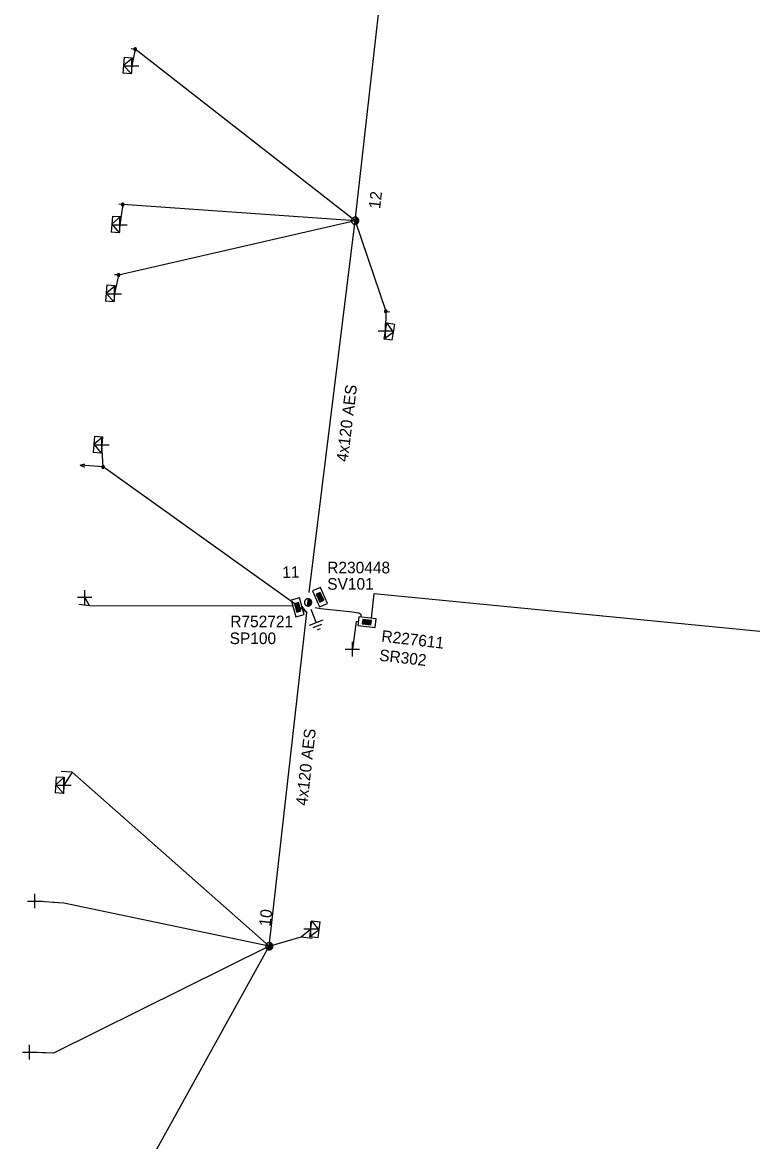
# Model space of a CAD drawing. Extents: x -544780 to -541582, y -1198995 to -1196551.
# Drawn here: x -543862.4 to -543799.3, y -1197255.8 to -1197159.1 of the extents above; entities that cross this region are included whole.
import ezdxf

# ---------------------------------------------------------------- set-up
doc = ezdxf.new("R2010")
doc.units = 0
for name, color, linetype in [('Vrstva 1', 7, 'Continuous'), ('Vrstva 13', 7, 'Continuous'), ('Vrstva 14', 7, 'Continuous'), ('Vrstva 15', 7, 'Continuous'), ('Vrstva 2', 7, 'Continuous'), ('Vrstva 28', 7, 'Continuous'), ('Vrstva 29', 7, 'Continuous'), ('Vrstva 30', 7, 'Continuous'), ('Vrstva 31', 7, 'Continuous'), ('Vrstva 34', 7, 'Continuous'), ('Vrstva 5', 7, 'Continuous'), ('Vrstva 50', 7, 'Continuous'), ('Vrstva 51', 7, 'Continuous'), ('Vrstva 52', 7, 'Continuous'), ('Vrstva 54', 7, 'Continuous'), ('Vrstva 59', 7, 'Continuous'), ('Vrstva 8', 7, 'Continuous'), ('Vrstva 9', 7, 'Continuous')]:
    doc.layers.add(name, color=color, linetype=linetype)

# ---------------------------------------------------------------- blocks, each defined once
blk = doc.blocks.new('NN440')
at = {"layer": 'Vrstva 2'}
for points in [[(0.63, 0), (0.63, 0.06), (0.62, 0.13), (0.6, 0.19), (0.58, 0.25), (0.55, 0.31), (0.51, 0.37), (0.47, 0.42), (0.42, 0.46), (0.37, 0.51), (0.32, 0.54), (0.26, 0.57), (0.2, 0.59), (0.13, 0.61), (0.07, 0.62), (0, 0.63), (-0.06, 0.62), (-0.13, 0.61), (-0.19, 0.59), (-0.26, 0.57), (-0.31, 0.54), (-0.37, 0.51), (-0.42, 0.46), (-0.47, 0.42), (-0.51, 0.37), (-0.54, 0.31), (-0.57, 0.25), (-0.6, 0.19), (-0.62, 0.13), (-0.63, 0.06), (-0.63, 0), (-0.63, -0.07), (-0.62, -0.14), (-0.6, -0.2), (-0.57, -0.26), (-0.54, -0.32), (-0.51, -0.37), (-0.47, -0.43), (-0.42, -0.47), (-0.37, -0.51), (-0.31, -0.55), (-0.26, -0.58), (-0.19, -0.6), (-0.13, -0.62), (-0.06, -0.63), (0, -0.63), (0.07, -0.63), (0.13, -0.62), (0.2, -0.6), (0.26, -0.58), (0.32, -0.55), (0.37, -0.51), (0.42, -0.47), (0.47, -0.43), (0.51, -0.37), (0.55, -0.32), (0.58, -0.26), (0.6, -0.2), (0.62, -0.14), (0.63, -0.07), (0.63, 0)], [(-0.63, 0), (0.63, 0)], [(-0.6, -0.18), (0.57, -0.18)], [(-0.51, -0.32), (0.5, -0.32)], [(-0.37, -0.47), (0.35, -0.47)]]:
    blk.add_lwpolyline(points, dxfattribs=at)
blk = doc.blocks.new('NN560')
at = {"layer": 'Vrstva 2'}
for points in [[(1.999, -0.001), (1.59, 0.141)], [(0, -0.001), (1.999, -0.001)], [(1.999, -0.001), (1.59, -0.134)]]:
    blk.add_lwpolyline(points, dxfattribs=at)
blk = doc.blocks.new('NN800')
at = {"layer": 'Vrstva 1'}
for points in [[(-0.442, 0.442), (0.442, -0.442)], [(-0.442, -0.442), (0.442, 0.442)]]:
    blk.add_lwpolyline(points, dxfattribs=at)
blk = doc.blocks.new('NN620')
at = {"layer": 'Vrstva 8'}
for points in [[(0.752, 0.004), (-0.748, 0.004)], [(-0.748, 0.004), (-0.748, -0.746)], [(0.752, -0.746), (0.752, 0.004)], [(-0.748, -0.746), (0.752, -0.746)], [(0.368, -0.18), (-0.376, -0.18)], [(-0.376, -0.18), (-0.376, -0.558)], [(-0.376, -0.558), (0.368, -0.558)], [(0.321, -0.227), (-0.329, -0.227)], [(-0.329, -0.227), (-0.329, -0.51)], [(-0.329, -0.51), (0.321, -0.51)], [(0.274, -0.274), (-0.281, -0.274)], [(-0.281, -0.274), (-0.281, -0.463)], [(-0.281, -0.463), (0.274, -0.463)], [(0.227, -0.321), (-0.234, -0.321)], [(-0.234, -0.321), (-0.234, -0.416)], [(-0.234, -0.416), (0.227, -0.416)], [(-0.193, -0.369), (0.185, -0.369)], [(0.227, -0.416), (0.227, -0.321)], [(0.274, -0.463), (0.274, -0.274)], [(0.321, -0.51), (0.321, -0.227)], [(0.368, -0.558), (0.368, -0.18)]]:
    blk.add_lwpolyline(points, dxfattribs=at)
blk = doc.blocks.new('NN630')
at = {"layer": 'Vrstva 9'}
for points in [[(-0.003, -0.7), (-0.703, 0)], [(-0.703, -0.7), (-0.703, 0), (0.697, 0), (0.697, -0.7)], [(-0.703, -0.7), (0.697, -0.7)], [(-0.003, -0.7), (0.697, 0)]]:
    blk.add_lwpolyline(points, dxfattribs=at)
blk = doc.blocks.new('NN810')
at = {"layer": 'Vrstva 14'}
for points in [[(0.004, -0.64), (0.004, -1.89)], [(0.629, -1.89), (-0.621, -1.89)], [(0.388, -2.2), (-0.399, -2.2)], [(0.004, -2.515), (-0.124, -2.515)], [(0.137, -2.515), (0.004, -2.515)]]:
    blk.add_lwpolyline(points, dxfattribs=at)
blk = doc.blocks.new('NN500')
at = {"layer": 'Vrstva 2'}
for points in [[(0, -0.24), (0.02, -0.23), (0.05, -0.23), (0.07, -0.22), (0.09, -0.22), (0.12, -0.2), (0.14, -0.19), (0.16, -0.18), (0.17, -0.16), (0.19, -0.14), (0.2, -0.12), (0.21, -0.1), (0.22, -0.07), (0.23, -0.05), (0.23, -0.02), (0.23, 0), (0.23, 0.02), (0.23, 0.05), (0.22, 0.07), (0.21, 0.1), (0.2, 0.12), (0.19, 0.14), (0.17, 0.16), (0.16, 0.17), (0.14, 0.19), (0.12, 0.2), (0.09, 0.21), (0.07, 0.22), (0.05, 0.23), (0.02, 0.23), (0, 0.23), (-0.03, 0.23), (-0.05, 0.23), (-0.07, 0.22), (-0.1, 0.21), (-0.12, 0.2), (-0.14, 0.19), (-0.16, 0.17), (-0.18, 0.16), (-0.19, 0.14), (-0.2, 0.12), (-0.22, 0.1), (-0.22, 0.07), (-0.23, 0.05), (-0.23, 0.02), (-0.24, 0), (-0.23, -0.02), (-0.23, -0.05), (-0.22, -0.07), (-0.22, -0.1), (-0.2, -0.12), (-0.19, -0.14), (-0.18, -0.16), (-0.16, -0.18), (-0.14, -0.19), (-0.12, -0.2), (-0.1, -0.22), (-0.07, -0.22), (-0.05, -0.23), (-0.03, -0.23), (0, -0.24)], [(0, -0.24), (0.02, -0.23), (0.05, -0.23), (0.07, -0.22), (0.09, -0.22), (0.12, -0.2), (0.14, -0.19), (0.16, -0.18), (0.17, -0.16), (0.19, -0.14), (0.2, -0.12), (0.21, -0.1), (0.22, -0.07), (0.23, -0.05), (0.23, -0.02), (0.23, 0), (0.23, 0.02), (0.23, 0.05), (0.22, 0.07), (0.21, 0.1), (0.2, 0.12), (0.19, 0.14), (0.17, 0.16), (0.16, 0.17), (0.14, 0.19), (0.12, 0.2), (0.09, 0.21), (0.07, 0.22), (0.05, 0.23), (0.02, 0.23), (0, 0.23), (-0.03, 0.23), (-0.05, 0.23), (-0.07, 0.22), (-0.1, 0.21), (-0.12, 0.2), (-0.14, 0.19), (-0.16, 0.17), (-0.18, 0.16), (-0.19, 0.14), (-0.2, 0.12), (-0.22, 0.1), (-0.22, 0.07), (-0.23, 0.05), (-0.23, 0.02), (-0.24, 0), (-0.23, -0.02), (-0.23, -0.05), (-0.22, -0.07), (-0.22, -0.1), (-0.2, -0.12), (-0.19, -0.14), (-0.18, -0.16), (-0.16, -0.18), (-0.14, -0.19), (-0.12, -0.2), (-0.1, -0.22), (-0.07, -0.22), (-0.05, -0.23), (-0.03, -0.23), (0, -0.24)], [(0, -0.21), (0.02, -0.2), (0.04, -0.2), (0.06, -0.2), (0.08, -0.19), (0.1, -0.18), (0.12, -0.17), (0.14, -0.15), (0.15, -0.14), (0.16, -0.12), (0.18, -0.1), (0.19, -0.08), (0.19, -0.06), (0.2, -0.04), (0.2, -0.02), (0.2, 0), (0.2, 0.02), (0.2, 0.04), (0.19, 0.06), (0.19, 0.08), (0.18, 0.1), (0.16, 0.12), (0.15, 0.14), (0.14, 0.15), (0.12, 0.17), (0.1, 0.18), (0.08, 0.19), (0.06, 0.19), (0.04, 0.2), (0.02, 0.2), (0, 0.2), (-0.02, 0.2), (-0.04, 0.2), (-0.06, 0.19), (-0.08, 0.19), (-0.1, 0.18), (-0.12, 0.17), (-0.14, 0.15), (-0.15, 0.14), (-0.17, 0.12), (-0.18, 0.1), (-0.19, 0.08), (-0.2, 0.06), (-0.2, 0.04), (-0.21, 0.02), (-0.21, 0), (-0.21, -0.02), (-0.2, -0.04), (-0.2, -0.06), (-0.19, -0.08), (-0.18, -0.1), (-0.17, -0.12), (-0.15, -0.14), (-0.14, -0.15), (-0.12, -0.17), (-0.1, -0.18), (-0.08, -0.19), (-0.06, -0.2), (-0.04, -0.2), (-0.02, -0.2), (0, -0.21)], [(0, -0.18), (0.02, -0.18), (0.04, -0.17), (0.05, -0.17), (0.07, -0.16), (0.09, -0.15), (0.1, -0.14), (0.12, -0.13), (0.13, -0.12), (0.14, -0.1), (0.15, -0.09), (0.16, -0.07), (0.17, -0.05), (0.17, -0.04), (0.17, -0.02), (0.17, 0), (0.17, 0.02), (0.17, 0.04), (0.17, 0.05), (0.16, 0.07), (0.15, 0.09), (0.14, 0.1), (0.13, 0.12), (0.12, 0.13), (0.1, 0.14), (0.09, 0.15), (0.07, 0.16), (0.05, 0.17), (0.04, 0.17), (0.02, 0.17), (0, 0.18), (-0.02, 0.17), (-0.04, 0.17), (-0.06, 0.17), (-0.07, 0.16), (-0.09, 0.15), (-0.1, 0.14), (-0.12, 0.13), (-0.13, 0.12), (-0.14, 0.1), (-0.15, 0.09), (-0.16, 0.07), (-0.17, 0.05), (-0.17, 0.04), (-0.18, 0.02), (-0.18, 0), (-0.18, -0.02), (-0.17, -0.04), (-0.17, -0.05), (-0.16, -0.07), (-0.15, -0.09), (-0.14, -0.1), (-0.13, -0.12), (-0.12, -0.13), (-0.1, -0.14), (-0.09, -0.15), (-0.07, -0.16), (-0.06, -0.17), (-0.04, -0.17), (-0.02, -0.18), (0, -0.18)], [(0, -0.15), (0.01, -0.15), (0.03, -0.14), (0.04, -0.14), (0.06, -0.13), (0.07, -0.13), (0.08, -0.12), (0.1, -0.11), (0.11, -0.1), (0.12, -0.09), (0.13, -0.07), (0.13, -0.06), (0.14, -0.05), (0.14, -0.03), (0.14, -0.02), (0.14, 0), (0.14, 0.01), (0.14, 0.03), (0.14, 0.04), (0.13, 0.06), (0.13, 0.07), (0.12, 0.09), (0.11, 0.1), (0.1, 0.11), (0.08, 0.12), (0.07, 0.13), (0.06, 0.13), (0.04, 0.14), (0.03, 0.14), (0.01, 0.14), (0, 0.15), (-0.02, 0.14), (-0.03, 0.14), (-0.05, 0.14), (-0.06, 0.13), (-0.07, 0.13), (-0.09, 0.12), (-0.1, 0.11), (-0.11, 0.1), (-0.12, 0.09), (-0.13, 0.07), (-0.13, 0.06), (-0.14, 0.04), (-0.14, 0.03), (-0.15, 0.01), (-0.15, 0), (-0.15, -0.02), (-0.14, -0.03), (-0.14, -0.05), (-0.13, -0.06), (-0.13, -0.07), (-0.12, -0.09), (-0.11, -0.1), (-0.1, -0.11), (-0.09, -0.12), (-0.07, -0.13), (-0.06, -0.13), (-0.05, -0.14), (-0.03, -0.14), (-0.02, -0.15), (0, -0.15)], [(0, -0.12), (0.01, -0.12), (0.02, -0.11), (0.03, -0.11), (0.05, -0.11), (0.06, -0.1), (0.07, -0.09), (0.08, -0.09), (0.09, -0.08), (0.09, -0.07), (0.1, -0.06), (0.11, -0.05), (0.11, -0.04), (0.11, -0.02), (0.11, -0.01), (0.12, 0), (0.11, 0.01), (0.11, 0.02), (0.11, 0.04), (0.11, 0.05), (0.1, 0.06), (0.09, 0.07), (0.09, 0.08), (0.08, 0.09), (0.07, 0.09), (0.06, 0.1), (0.05, 0.11), (0.03, 0.11), (0.02, 0.11), (0.01, 0.12), (0, 0.12), (-0.01, 0.12), (-0.03, 0.11), (-0.04, 0.11), (-0.05, 0.11), (-0.06, 0.1), (-0.07, 0.09), (-0.08, 0.09), (-0.09, 0.08), (-0.1, 0.07), (-0.1, 0.06), (-0.11, 0.05), (-0.11, 0.04), (-0.12, 0.02), (-0.12, 0.01), (-0.12, 0), (-0.12, -0.01), (-0.12, -0.02), (-0.11, -0.04), (-0.11, -0.05), (-0.1, -0.06), (-0.1, -0.07), (-0.09, -0.08), (-0.08, -0.09), (-0.07, -0.09), (-0.06, -0.1), (-0.05, -0.11), (-0.04, -0.11), (-0.03, -0.11), (-0.01, -0.12), (0, -0.12)], [(0, -0.09), (0.01, -0.09), (0.02, -0.09), (0.03, -0.08), (0.03, -0.08), (0.04, -0.08), (0.05, -0.07), (0.06, -0.07), (0.06, -0.06), (0.07, -0.05), (0.07, -0.04), (0.08, -0.04), (0.08, -0.03), (0.08, -0.02), (0.09, -0.01), (0.09, 0), (0.09, 0.01), (0.08, 0.02), (0.08, 0.03), (0.08, 0.03), (0.07, 0.04), (0.07, 0.05), (0.06, 0.06), (0.06, 0.06), (0.05, 0.07), (0.04, 0.07), (0.03, 0.08), (0.03, 0.08), (0.02, 0.08), (0.01, 0.09), (0, 0.09), (-0.01, 0.09), (-0.02, 0.08), (-0.03, 0.08), (-0.04, 0.08), (-0.04, 0.07), (-0.05, 0.07), (-0.06, 0.06), (-0.07, 0.06), (-0.07, 0.05), (-0.08, 0.04), (-0.08, 0.03), (-0.08, 0.03), (-0.09, 0.02), (-0.09, 0.01), (-0.09, 0), (-0.09, -0.01), (-0.09, -0.02), (-0.08, -0.03), (-0.08, -0.04), (-0.08, -0.04), (-0.07, -0.05), (-0.07, -0.06), (-0.06, -0.07), (-0.05, -0.07), (-0.04, -0.08), (-0.04, -0.08), (-0.03, -0.08), (-0.02, -0.09), (-0.01, -0.09), (0, -0.09)], [(0, -0.06), (0, -0.06), (0.01, -0.06), (0.02, -0.05), (0.02, -0.05), (0.03, -0.05), (0.03, -0.05), (0.04, -0.04), (0.04, -0.04), (0.05, -0.03), (0.05, -0.03), (0.05, -0.02), (0.05, -0.02), (0.05, -0.01), (0.06, -0.01), (0.06, 0), (0.06, 0.01), (0.05, 0.01), (0.05, 0.02), (0.05, 0.02), (0.05, 0.03), (0.05, 0.03), (0.04, 0.04), (0.04, 0.04), (0.03, 0.05), (0.03, 0.05), (0.02, 0.05), (0.02, 0.05), (0.01, 0.06), (0, 0.06), (0, 0.06), (-0.01, 0.06), (-0.01, 0.06), (-0.02, 0.05), (-0.02, 0.05), (-0.03, 0.05), (-0.03, 0.05), (-0.04, 0.04), (-0.04, 0.04), (-0.05, 0.03), (-0.05, 0.03), (-0.05, 0.02), (-0.06, 0.02), (-0.06, 0.01), (-0.06, 0.01), (-0.06, 0), (-0.06, -0.01), (-0.06, -0.01), (-0.06, -0.02), (-0.05, -0.02), (-0.05, -0.03), (-0.05, -0.03), (-0.04, -0.04), (-0.04, -0.04), (-0.03, -0.05), (-0.03, -0.05), (-0.02, -0.05), (-0.02, -0.05), (-0.01, -0.06), (-0.01, -0.06), (0, -0.06)], [(0, -0.03), (0, -0.03), (0, -0.03), (0.01, -0.03), (0.01, -0.03), (0.01, -0.02), (0.02, -0.02), (0.02, -0.02), (0.02, -0.02), (0.02, -0.02), (0.02, -0.01), (0.02, -0.01), (0.03, -0.01), (0.03, -0.01), (0.03, 0), (0.03, 0), (0.03, 0), (0.03, 0.01), (0.03, 0.01), (0.02, 0.01), (0.02, 0.01), (0.02, 0.02), (0.02, 0.02), (0.02, 0.02), (0.02, 0.02), (0.01, 0.02), (0.01, 0.02), (0.01, 0.03), (0, 0.03), (0, 0.03), (0, 0.03), (0, 0.03), (-0.01, 0.03), (-0.01, 0.03), (-0.01, 0.02), (-0.02, 0.02), (-0.02, 0.02), (-0.02, 0.02), (-0.02, 0.02), (-0.02, 0.02), (-0.03, 0.01), (-0.03, 0.01), (-0.03, 0.01), (-0.03, 0.01), (-0.03, 0), (-0.03, 0), (-0.03, 0), (-0.03, -0.01), (-0.03, -0.01), (-0.03, -0.01), (-0.03, -0.01), (-0.02, -0.02), (-0.02, -0.02), (-0.02, -0.02), (-0.02, -0.02), (-0.02, -0.02), (-0.01, -0.03), (-0.01, -0.03), (-0.01, -0.03), (0, -0.03), (0, -0.03)], [(0.23, 0), (0.7, 0)]]:
    blk.add_lwpolyline(points, dxfattribs=at)
blk = doc.blocks.new('NN510')
at = {"layer": 'Vrstva 2'}
blk.add_lwpolyline([(0.001, 0.002), (0.001, 0.939)], dxfattribs=at)

msp = doc.modelspace()

# ---------------------------------------------------------------- linework, layer by layer
at = {"layer": 'Vrstva 5'}
msp.add_lwpolyline([(-543837.124, -1197209.675), (-543836.658, -1197209.748), (-543834.156, -1197210.005), (-543833.342, -1197210.137), (-543833.188, -1197210.236), (-543833.186, -1197210.5)], dxfattribs=at)
at = {"layer": 'Vrstva 50'}
for points in [[(-543837.625, -1197208.372), (-543833.669, -1197176.26), (-543830.03, -1197144.12), (-543825.63, -1197110.859), (-543822.01, -1197079.019), (-543818.84, -1197052.008), (-543814.82, -1197018.239), (-543812.847, -1196994.699)], [(-543837.836, -1197210.101), (-543838.273, -1197209.553)], [(-543840.42, -1197347.53), (-543854.759, -1197329.329), (-543856.46, -1197300.73), (-543856.72, -1197267.15), (-543841.08, -1197238.92), (-543837.836, -1197210.101)]]:
    msp.add_lwpolyline(points, dxfattribs=at)
at = {"layer": 'Vrstva 52'}
msp.add_lwpolyline([(-543832.24, -1197210.609), (-543832.012, -1197208.446), (-543784.287, -1197213.107), (-543783.69, -1197208.582)], dxfattribs=at)
at = {"layer": 'Vrstva 54'}
for points in [[(-543833.669, -1197176.26), (-543854.092, -1197180.948), (-543854.457, -1197182.564)], [(-543833.669, -1197176.26), (-543831.026, -1197184.079), (-543831.042, -1197185.778)]]:
    msp.add_lwpolyline(points, dxfattribs=at)
at = {"layer": 'Vrstva 59'}
msp.add_lwpolyline([(-543833.404, -1197210.896), (-543833.586, -1197210.877), (-543833.901, -1197213.269)], dxfattribs=at)
at = {"layer": 'Vrstva 8'}
for points in [[(-543833.669, -1197176.26), (-543852.661, -1197161.446), (-543852.96, -1197162.877)], [(-543833.669, -1197176.26), (-543853.734, -1197174.865), (-543853.982, -1197176.608)], [(-543837.836, -1197210.101), (-543855.43, -1197197.524), (-543855.532, -1197195.626)], [(-543838.977, -1197209.549), (-543856.592, -1197209.512), (-543857.014, -1197208.78)], [(-543841.08, -1197238.92), (-543858.111, -1197223.887), (-543858.823, -1197225.02)], [(-543841.08, -1197238.92), (-543858.824, -1197235.194), (-543861.327, -1197235.015)], [(-543841.08, -1197238.92), (-543838.317, -1197238.097), (-543837.481, -1197237.421)], [(-543841.08, -1197238.92), (-543859.718, -1197248.166), (-543861.774, -1197248.076)]]:
    msp.add_lwpolyline(points, dxfattribs=at)

# ---------------------------------------------------------------- block references
at = {"layer": 'Vrstva 13'}
for name, p, xscale, yscale, rotation in [('NN500', (-543852.661, -1197161.446), 0.4999999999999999, 0.49999999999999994, 175.3009999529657), ('NN500', (-543853.734, -1197174.865), 0.5000000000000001, 0.5, 175.79799998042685), ('NN440', (-543833.67, -1197176.259), 0.5, 0.5000000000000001, 83.01446670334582), ('NN500', (-543854.092, -1197180.948), 0.5, 0.49999999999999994, 175.26399991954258), ('NN500', (-543831.026, -1197184.079), 0.5, 0.49999999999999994, -8.745999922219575), ('NN500', (-543855.43, -1197197.524), 0.5000000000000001, 0.5, 175.31999998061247), ('NN440', (-543837.73, -1197209.219), 0.5, 0.49999999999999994, 82.96938608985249), ('NN440', (-543841.08, -1197238.919), 0.5, 0.5, 83.63215273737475)]:
    msp.add_blockref(name, p, dxfattribs=dict(at, xscale=xscale, yscale=yscale, rotation=rotation))
for name, p, rotation in [('NN560', (-543855.43, -1197197.524), 175.3201750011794), ('NN510', (-543856.592, -1197209.513), 82.81437501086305), ('NN510', (-543858.111, -1197223.887), 87.0927389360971), ('NN510', (-543858.824, -1197235.195), 86.46965277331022), ('NN510', (-543838.318, -1197238.096), -96.94551112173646), ('NN510', (-543859.717, -1197248.167), 87.05653335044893)]:
    msp.add_blockref(name, p, dxfattribs=dict(at, rotation=rotation))
at = {"layer": 'Vrstva 15', "rotation": 21.168366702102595}
msp.add_blockref('NN810', (-543837.729, -1197209.218), dxfattribs=at)
at = {"layer": 'Vrstva 28'}
for p, rotation in [((-543837.042, -1197208.92), 113.4430000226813), ((-543838.273, -1197209.553), -73.8399472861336), ((-543832.613, -1197210.566), -6.580630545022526)]:
    msp.add_blockref('NN620', p, dxfattribs=dict(at, rotation=rotation))
at = {"layer": 'Vrstva 31'}
for p, rotation in [((-543852.96, -1197162.877), -94.69930275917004), ((-543853.982, -1197176.608), -94.20242503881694), ((-543854.457, -1197182.565), -94.73558331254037), ((-543831.042, -1197185.779), 81.2538388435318), ((-543855.532, -1197195.626), -94.67982498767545), ((-543858.823, -1197225.02), -92.90726105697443), ((-543837.481, -1197237.421), 82.90159441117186)]:
    msp.add_blockref('NN630', p, dxfattribs=dict(at, rotation=rotation))
at = {"layer": 'Vrstva 34'}
for p, rotation in [((-543852.96, -1197162.876), 45), ((-543853.982, -1197176.607), 45), ((-543854.457, -1197182.564), 45), ((-543831.042, -1197185.778), 45), ((-543855.532, -1197195.625), 45), ((-543857.014, -1197208.78), 45), ((-543833.901, -1197213.269), 44.99999995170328), ((-543858.823, -1197225.019), 45), ((-543861.327, -1197235.015), 45), ((-543837.481, -1197237.421), 45), ((-543861.774, -1197248.076), 45)]:
    msp.add_blockref('NN800', p, dxfattribs=dict(at, rotation=rotation))

# ---------------------------------------------------------------- texts
at = {"layer": 'Vrstva 14'}
for s, rotation, p in [('12', 83.014, (-543831.516, -1197175.261)), ('11', 1.133, (-543839.953, -1197207.118)), ('10', 83.632, (-543840.98, -1197237.259))]:
    msp.add_text(s, height=1, rotation=rotation, dxfattribs=at).set_placement(p)
at = {"layer": 'Vrstva 29'}
for s, rotation, p in [('R230448', 359.917, (-543836.076, -1197206.711)), ('R227611', 353.419, (-543831.44, -1197212.608))]:
    msp.add_text(s, height=1, rotation=rotation, dxfattribs=at).set_placement(p)
msp.add_text('R752721', height=1, dxfattribs=at).set_placement((-543844.449, -1197211.367))
at = {"layer": 'Vrstva 30'}
for s, rotation, p in [('SV101', 0.16, (-543836.074, -1197208.13)), ('SR302', 353.419, (-543831.63, -1197214.255))]:
    msp.add_text(s, height=1, rotation=rotation, dxfattribs=at).set_placement(p)
msp.add_text('SP100', height=1, dxfattribs=at).set_placement((-543844.505, -1197212.823))
at = {"layer": 'Vrstva 51'}
for rotation, p in [(82.977, (-543834.312, -1197197.122)), (83.578, (-543837.804, -1197226.825))]:
    msp.add_text('4x120 AES', height=1, rotation=rotation, dxfattribs=at).set_placement(p)

doc.saveas('drawing.dxf')
